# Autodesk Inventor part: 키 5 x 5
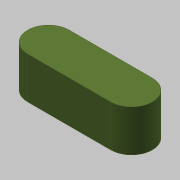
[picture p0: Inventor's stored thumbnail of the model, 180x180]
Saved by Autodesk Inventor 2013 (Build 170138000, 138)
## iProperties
Created: 2011-04
Part Number: 키 5 x 5
Document SubType Name: Modeling
Designer: pww
Density: 7.86 g/cm^3
Material: 강철, 연강
Author: pww
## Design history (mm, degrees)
sketch "스케치1"
  geometry: L1 (-5, -2.5)-(5, -2.5); L2 (5, 2.5)-(-5, 2.5); A1 r 2.5 centre (-5, 0) between (-5, 2.5) and (-5, -2.5); A2 r 2.5 centre (5, 0) between (5, -2.5) and (5, 2.5); 1 further point
  constraints: 4 end point, 4 point on circle, 2 centre point
extrude "돌출1" new body sketch "스케치1" distance "d0" = 5; taper "d1" = 0 deg
node "솔리드1"
